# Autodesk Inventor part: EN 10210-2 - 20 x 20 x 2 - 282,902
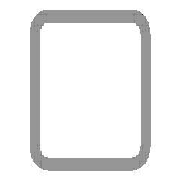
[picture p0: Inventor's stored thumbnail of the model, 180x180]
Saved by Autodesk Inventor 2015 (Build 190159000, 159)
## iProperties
Created: 2015-05
Part Number: EN 10210-2 - 20 x 20 x 2 - 282,902
Material: Steel, Mild
Description: Tube
Document SubType Name: Modeling
Standard: DIN
Designer: TREINA6
Standard Revision: 1997
Standards Organization: DIN
Language: en-US
Size Designation: 20 x 20 x 2
Categories: <MemberInstance><Categories><Category DisplayName="Structural Shapes" InternalName="089c4875-fa83-4c05-b084-43b9cc11f5ed" Mnemonic="GRDR"><CategoryParameter Dis
Stock Number: 20 x 20 x 2
Density: 7.85 g/cm^3
Appearance: Semi-Polished
_CCFamilyMember: 1
_CCFamilyDisplayName: DIN EN 10210-2 (Square) - Tube
_FrameMemberDoc: Frame Member File
_Version: 15.0.0
_GetPNFromCC: 1
G_L: 282,902 mm
G_W: 20,000 mm
G_H: 20,000 mm
IsCustomPart: 1
Author: TREINA6
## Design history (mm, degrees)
node "Start plane"
node "End plane"
sketch "Sketch"
  geometry: L1 (-10, -7)-(-10, 7); L2 (-7, 10)-(7, 10); L3 (10, 7)-(10, -7); L4 (7, -10)-(-7, -10); L5 (-7, 8)-(7, 8); L6 (8, 7)-(8, -7); L7 (7, -8)-(-7, -8); L8 (-8, -7)-(-8, 7); L9 (0, 14.87)-(0, -14.87) reference; L10 (-14.87, 0)-(14.87, 0) reference; A1 r 3 centre (-7, -7) between (-10, -7) and (-7, -10); A2 r 3 centre (-7, 7) between (-7, 10) and (-10, 7); A3 r 3 centre (7, 7) between (10, 7) and (7, 10); A4 r 3 centre (7, -7) between (7, -10) and (10, -7); A5 r 1 centre (-7, 7) between (-7, 8) and (-8, 7); A6 r 1 centre (7, 7) between (8, 7) and (7, 8); A7 r 1 centre (7, -7) between (7, -8) and (8, -7); A8 r 1 centre (-7, -7) between (-8, -7) and (-7, -8)
  constraints: 16 end point, 16 point on circle, 8 centre point, 8 tangent, 4 parallel, 3 equal radius, 2 perpendicular, 7 other
  dimensions: "d7" = 3 radius of A1 (= G_IR); "d10" = 20 distance between parallel lines of L2 L4 (= G_H); "d11" = 20 distance between parallel lines of L1 L3 (= G_W); "d12" = 2 distance between parallel lines of L3 L6 (= G_T); "d15" = 10 distance between parallel lines of L2 L10 (= 0.5 x d10); "d16" = 10 distance between parallel lines of L9 L3 (= 0.5 x d11)
extrude "Body" new body sketch "Sketch" stored distance "d3" = 282.90163 (= G_L); taper "d4" = 0 deg
node "Driven Length"
  sketch "Sketch3"
    geometry: L1 (0, 0)-(10, 0) reference
    constraints: 2 end point, 1 horizontal
  workplane "Work Plane3"
  sketch "Sketch4"
    geometry: L1 (-2, 0)-(12, 0) reference; L2 (-2, 282.902)-(12, 282.902) reference
    dimensions: "d18" = 282.90163 distance between parallel lines of L1 L2 (derived)
body "Solid1"
other parameters: "G_W" = 20 [user parameter; used in 1 equation term], "G_H" = 20 [user parameter; used in 1 equation term], "G_T" = 2 [user parameter; used in 1 equation term], "G_IR" = 3 [user parameter; used in 1 equation term], "G_L" = 282.90163 (= d18) [user parameter; used in 1 equation term], "G_OFFSET_START" = 0 [user parameter; used in 1 equation term], "G_OFFSET_END" = 0 [user parameter; used in 1 equation term], "d13" = 0 (computed from G_OFFSET_START), "d14" = 282.90163 (= G_OFFSET_END + B_L), "B_L" = 282.90163 [user parameter; used in 1 equation term], "d17" = 90 deg
